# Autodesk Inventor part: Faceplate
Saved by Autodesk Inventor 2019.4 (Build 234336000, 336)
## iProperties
Created: 2021-08
Part Number: Faceplate
Material: Generic
Document SubType Name: Modeling
Designer: Administrator
Density: 1 g/cm^3
Appearance: Default
Title: Faceplate v7
Author: Administrator
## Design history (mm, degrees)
feature "Body1"
body "Solid1"
